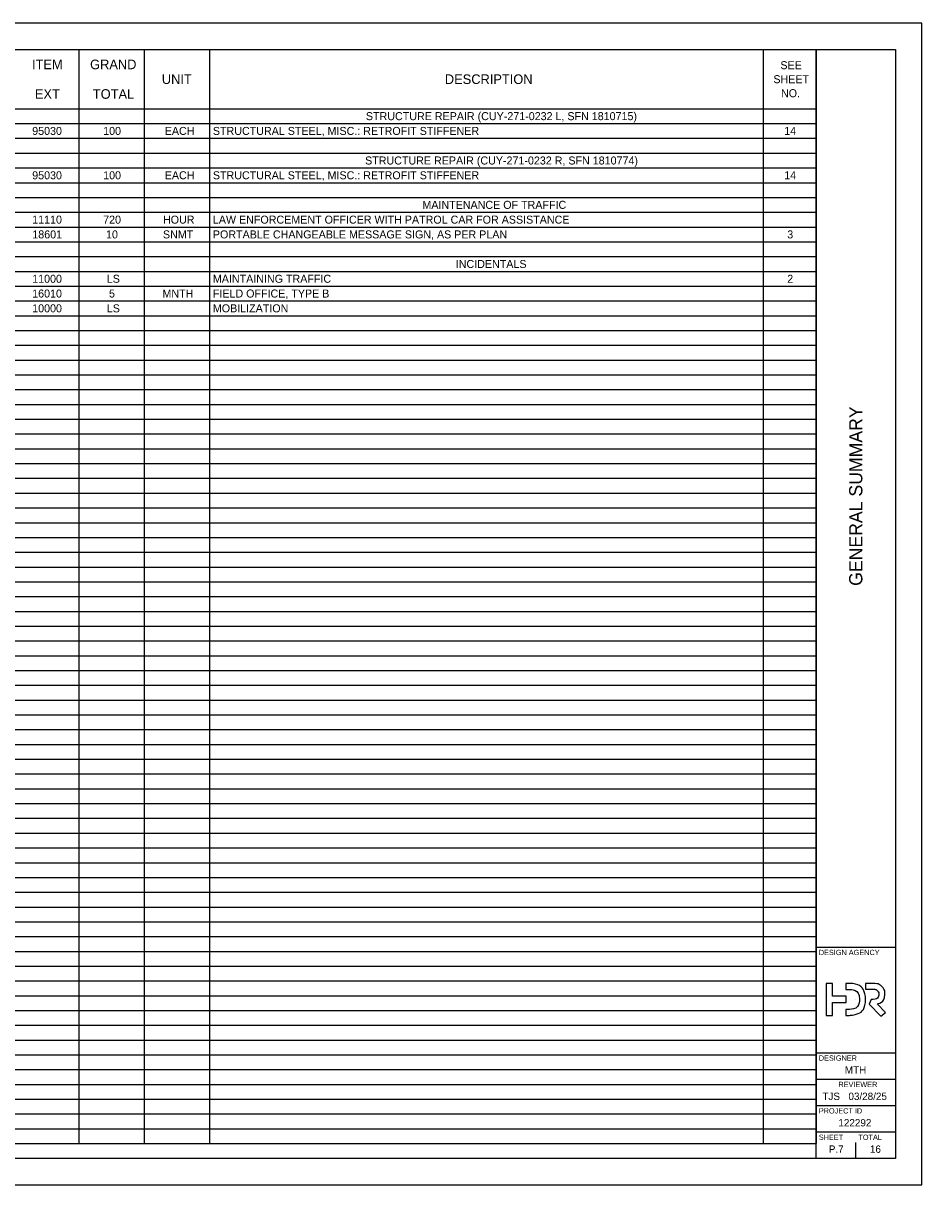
# Model space of a CAD drawing. Extents: x 0 to 34, y 0 to 22.
# Drawn here: x 16.98 to 34, y 0 to 22 of the extents above; entities that cross this region are included whole.
import ezdxf

# ---------------------------------------------------------------- set-up
doc = ezdxf.new("R2010")
doc.units = 0
for name, color, linetype in [('SH_Border', 7, 'Continuous'), ('SH_Cut_Line', 7, 'Continuous'), ('SH_Data', 7, 'Continuous'), ('SH_Text', 7, 'Continuous')]:
    doc.layers.add(name, color=color, linetype=linetype)

msp = doc.modelspace()

# ---------------------------------------------------------------- linework, layer by layer
at = {"layer": 'SH_Border'}
for p, q in [((32, 0.5), (32, 21.5)), ((32, 4.5), (33.5, 4.5)), ((32, 2.5), (33.5, 2.5)), ((32, 2), (33.5, 2)), ((32, 1.5), (33.5, 1.5)), ((32, 1), (33.5, 1))]:
    msp.add_line(p, q, dxfattribs=at)
msp.add_lwpolyline([(1.5, 21.5), (33.5, 21.5), (33.5, 0.5), (1.5, 0.5)], close=True, dxfattribs=at)
at = {"layer": 'SH_Cut_Line'}
msp.add_lwpolyline([(0, 0), (34, 0), (34, 22), (0, 22)], close=True, dxfattribs=at)
at = {"layer": 'SH_Data'}
for p, q in [((32.75, 3.5), (32.75, 3.5)), ((32.375, 0.675), (32.375, 0.675)), ((32.75, 0.5), (32.75, 0.8))]:
    msp.add_line(p, q, dxfattribs=at)
msp.add_lwpolyline([(32.56531, 3.57144), (32.31122, 3.57144), (32.31122, 3.81294), (32.1888, 3.81294), (32.1888, 3.20896), (32.31122, 3.20896), (32.31122, 3.45062), (32.56531, 3.45062)], close=True, dxfattribs=at)
for points in [[(32.63352, 3.81295), (32.56214, 3.81295), (32.56214, 3.69955), (32.63352, 3.69955)], [(33.06338, 3.81294), (32.93548, 3.81294), (32.93548, 3.70429), (33.07186, 3.70429)], [(32.63352, 3.32232), (32.56214, 3.32232), (32.56214, 3.20894), (32.63352, 3.20894)], [(32.93561, 3.51096), (32.93564, 3.51096), (32.93564, 3.51128), (32.93564, 3.51162), (32.93561, 3.51162)], [(33.07739, 3.50994), (33.04333, 3.50994), (33.00336, 3.42366), (33.22643, 3.19237), (33.31322, 3.26519), (33.15509, 3.42477)]]:
    msp.add_lwpolyline(points, dxfattribs=at)
for points in [[(32.93561, 3.51162), (32.93561, 3.51162), (32.93521, 3.68627), (32.80832, 3.81295), (32.63352, 3.81295)], [(33.23928, 3.75864), (33.23928, 3.75864), (33.19278, 3.80241), (33.14112, 3.81294), (33.06338, 3.81294)], [(33.30203, 3.60494), (33.30203, 3.60494), (33.30203, 3.66792), (33.28412, 3.71645), (33.23928, 3.75864)], [(32.63352, 3.69955), (32.63352, 3.69955), (32.74449, 3.69955), (32.82201, 3.62216), (32.82224, 3.51128)], [(33.07186, 3.70429), (33.07186, 3.70429), (33.11298, 3.70429), (33.14082, 3.69567), (33.16089, 3.67593)], [(33.18871, 3.60733), (33.18871, 3.60733), (33.18871, 3.54627), (33.13606, 3.50994), (33.07739, 3.50994)], [(33.15509, 3.42477), (33.15509, 3.42477), (33.24248, 3.44104), (33.30203, 3.52085), (33.30203, 3.60494)], [(33.16089, 3.67593), (33.16089, 3.67593), (33.17921, 3.65791), (33.18871, 3.63415), (33.18871, 3.60733)], [(32.82224, 3.51128), (32.82224, 3.51128), (32.82201, 3.40042), (32.74449, 3.32232), (32.63352, 3.32232)], [(32.63352, 3.20894), (32.63352, 3.20894), (32.80832, 3.20894), (32.93521, 3.33631), (32.93561, 3.51096)]]:
    msp.add_open_spline(points, degree=3, dxfattribs=at)
at = {"layer": 'SH_Text'}
for p, q in [((1.5, 21.5), (32.00244, 21.5)), ((18.03588, 21.5), (18.03588, 0.78074)), ((19.27113, 21.5), (19.27113, 0.78074)), ((20.50638, 21.5), (20.50638, 0.78074)), ((30.99777, 21.5), (30.99777, 0.78074)), ((32.00244, 21.5), (32.00244, 0.78074)), ((1.5, 20.38004), (32.00244, 20.38004)), ((1.5, 20.10005), (32.00244, 20.10005)), ((1.5, 19.82006), (32.00244, 19.82006)), ((1.5, 19.54007), (32.00244, 19.54007)), ((1.5, 19.26008), (32.00244, 19.26008)), ((1.5, 18.98009), (32.00244, 18.98009)), ((1.5, 18.7001), (32.00244, 18.7001)), ((1.5, 18.42011), (32.00244, 18.42011)), ((1.5, 18.14012), (32.00244, 18.14012)), ((1.5, 17.86013), (32.00244, 17.86013)), ((1.5, 17.58014), (32.00244, 17.58014)), ((1.5, 17.30015), (32.00244, 17.30015)), ((1.5, 17.02016), (32.00244, 17.02016)), ((1.5, 16.74017), (32.00244, 16.74017)), ((1.5, 16.46018), (32.00244, 16.46018)), ((1.5, 16.18019), (32.00244, 16.18019)), ((1.5, 15.9002), (32.00244, 15.9002)), ((1.5, 15.62021), (32.00244, 15.62021)), ((1.5, 15.34022), (32.00244, 15.34022)), ((1.5, 15.06023), (32.00244, 15.06023)), ((1.5, 14.78024), (32.00244, 14.78024)), ((1.5, 14.50025), (32.00244, 14.50025)), ((1.5, 14.22026), (32.00244, 14.22026)), ((1.5, 13.94027), (32.00244, 13.94027)), ((1.5, 13.66028), (32.00244, 13.66028)), ((1.5, 13.38029), (32.00244, 13.38029)), ((1.5, 13.1003), (32.00244, 13.1003)), ((1.5, 12.82031), (32.00244, 12.82031)), ((1.5, 12.54032), (32.00244, 12.54032)), ((1.5, 12.26033), (32.00244, 12.26033)), ((1.5, 11.98034), (32.00244, 11.98034)), ((1.5, 11.70035), (32.00244, 11.70035)), ((1.5, 11.42036), (32.00244, 11.42036)), ((1.5, 11.14037), (32.00244, 11.14037)), ((1.5, 10.86038), (32.00244, 10.86038)), ((1.5, 10.58039), (32.00244, 10.58039)), ((1.5, 10.3004), (32.00244, 10.3004)), ((1.5, 10.02041), (32.00244, 10.02041)), ((1.5, 9.74042), (32.00244, 9.74042)), ((1.5, 9.46043), (32.00244, 9.46043)), ((1.5, 9.18044), (32.00244, 9.18044)), ((1.5, 8.90045), (32.00244, 8.90045)), ((1.5, 8.62046), (32.00244, 8.62046)), ((1.5, 8.34047), (32.00244, 8.34047)), ((1.5, 8.06048), (32.00244, 8.06048)), ((1.5, 7.78049), (32.00244, 7.78049)), ((1.5, 7.5005), (32.00244, 7.5005)), ((1.5, 7.22051), (32.00244, 7.22051)), ((1.5, 6.94052), (32.00244, 6.94052)), ((1.5, 6.66053), (32.00244, 6.66053)), ((1.5, 6.38054), (32.00244, 6.38054)), ((1.5, 6.10055), (32.00244, 6.10055)), ((1.5, 5.82056), (32.00244, 5.82056)), ((1.5, 5.54057), (32.00244, 5.54057)), ((1.5, 5.26058), (32.00244, 5.26058)), ((1.5, 4.98059), (32.00244, 4.98059)), ((1.5, 4.7006), (32.00244, 4.7006)), ((1.5, 4.42061), (32.00244, 4.42061)), ((1.5, 4.14062), (32.00244, 4.14062)), ((1.5, 3.86063), (32.00244, 3.86063)), ((1.5, 3.58064), (32.00244, 3.58064)), ((1.5, 3.30065), (32.00244, 3.30065)), ((1.5, 3.02066), (32.00244, 3.02066)), ((1.5, 2.74067), (32.00244, 2.74067)), ((1.5, 2.46068), (32.00244, 2.46068)), ((1.5, 2.18069), (32.00244, 2.18069)), ((1.5, 1.9007), (32.00244, 1.9007)), ((1.5, 1.62071), (32.00244, 1.62071)), ((1.5, 1.34072), (32.00244, 1.34072)), ((1.5, 1.06073), (32.00244, 1.06073)), ((1.5, 0.78074), (32.00244, 0.78074))]:
    msp.add_line(p, q, dxfattribs=at)

# ---------------------------------------------------------------- texts
at = {"layer": 'SH_Data'}
msp.add_text('GENERAL SUMMARY', height=0.25, rotation=90, dxfattribs=at).set_placement((32.875, 11.34354))
for s, height, p in [('DESIGN AGENCY', 0.1, (32.05, 4.35)), ('DESIGNER', 0.1, (32.05, 2.35)), ('MTH', 0.14, (32.54243, 2.105)), ('REVIEWER', 0.1, (32.42183, 1.85)), ('TJS', 0.14, (32.11789, 1.605)), ('03/28/25', 0.14, (32.61105, 1.605)), ('PROJECT ID', 0.1, (32.05, 1.35)), ('122292', 0.14, (32.4209, 1.105)), ('SHEET', 0.1, (32.05, 0.85)), ('TOTAL', 0.1, (32.8, 0.85)), ('P.7', 0.14, (32.23934, 0.605)), ('16', 0.14, (33.0176, 0.605))]:
    msp.add_text(s, height=height, dxfattribs=at).set_placement(p)
at = {"layer": 'SH_Text'}
for s, height, p in [('ITEM', 0.181829, (17.1466, 21.1291)), ('GRAND', 0.181829, (18.24673, 21.1291)), ('SEE ', 0.151524, (31.32265, 21.12943)), ('UNIT', 0.181829, (19.60548, 20.84911)), ('DESCRIPTION', 0.1818288, (24.96651, 20.84911)), ('SHEET ', 0.151524, (31.18912, 20.86426)), ('EXT', 0.181829, (17.20064, 20.56912)), ('TOTAL', 0.181829, (18.29863, 20.56912)), ('NO.', 0.151524, (31.33362, 20.59909)), ('STRUCTURE REPAIR (CUY-271-0232 L, SFN 1810715)', 0.151524, (23.4707, 20.16428)), ('95030', 0.151524, (17.14987, 19.88429)), ('100', 0.151524, (18.49396, 19.88429)), ('EACH', 0.151524, (19.66083, 19.88429)), ('STRUCTURAL STEEL, MISC.: RETROFIT STIFFENER', 0.151524, (20.57226, 19.88429)), ('14', 0.151524, (31.39434, 19.88429)), ('STRUCTURE REPAIR (CUY-271-0232 R, SFN 1810774)', 0.151524, (23.45565, 19.32431)), ('95030', 0.151524, (17.14987, 19.04432)), ('100', 0.151524, (18.49396, 19.04432)), ('EACH', 0.151524, (19.66083, 19.04432)), ('STRUCTURAL STEEL, MISC.: RETROFIT STIFFENER', 0.151524, (20.57226, 19.04432)), ('14', 0.151524, (31.39434, 19.04432)), ('MAINTENANCE OF TRAFFIC', 0.151524, (24.54125, 18.48434)), ('11110', 0.151524, (17.14987, 18.20435)), ('720', 0.151524, (18.49396, 18.20435)), ('HOUR', 0.151524, (19.62747, 18.20435)), ('LAW ENFORCEMENT OFFICER WITH PATROL CAR FOR ASSISTANCE', 0.151524, (20.57226, 18.20435)), ('18601', 0.151524, (17.15198, 17.92436)), ('10', 0.151524, (18.54838, 17.92436)), ('SNMT', 0.151524, (19.62664, 17.92436)), ('PORTABLE CHANGEABLE MESSAGE SIGN, AS PER PLAN', 0.151524, (20.57226, 17.92436)), ('3', 0.15152, (31.45221, 17.92436)), ('INCIDENTALS', 0.151524, (25.17336, 17.36438)), ('11000', 0.151524, (17.14987, 17.08439)), ('LS', 0.151524, (18.56291, 17.08439)), ('MAINTAINING TRAFFIC', 0.151524, (20.57226, 17.08439)), ('2', 0.15152, (31.45164, 17.08439)), ('16010', 0.151524, (17.14987, 16.8044)), ('5', 0.15152, (18.60536, 16.8044)), ('MNTH', 0.151524, (19.61723, 16.8044)), ('FIELD OFFICE, TYPE B', 0.151524, (20.57226, 16.8044)), ('10000', 0.151524, (17.14987, 16.52441)), ('LS', 0.151524, (18.56291, 16.52441)), ('MOBILIZATION', 0.151524, (20.57226, 16.52441))]:
    msp.add_text(s, height=height, dxfattribs=at).set_placement(p)

doc.saveas('drawing.dxf')
